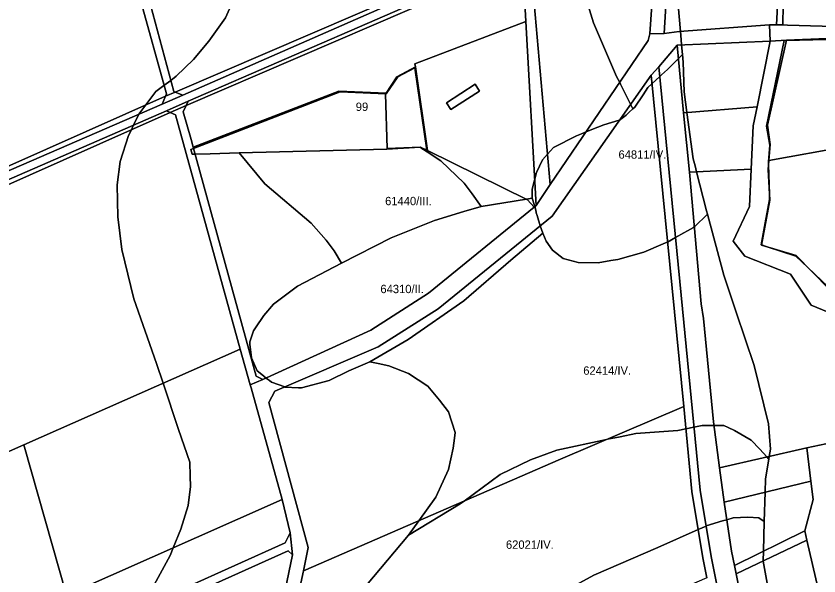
# Model space of a CAD drawing. Extents: x -522079 to -518833, y -1142400 to -1139961.
# Drawn here: x -520985.3 to -520504.9, y -1141508 to -1141173.1 of the extents above; entities that cross this region are included whole.
import ezdxf

# ---------------------------------------------------------------- set-up
doc = ezdxf.new("R2010")
doc.units = 0
for name, color, linetype in [('95560013', 7, 'Continuous'), ('95600013', 7, 'Continuous'), ('95610013', 7, 'Continuous'), ('95620013', 7, 'Continuous'), ('95630013', 7, 'Continuous'), ('95640013', 7, 'Continuous'), ('95660013', 7, 'Continuous')]:
    doc.layers.add(name, color=color, linetype=linetype)

msp = doc.modelspace()

# ---------------------------------------------------------------- linework, layer by layer
at = {"layer": '95560013'}
for points in [[(-520948.18, -1141008.97), (-520939.75, -1141038.42), (-520928.14, -1141079.25), (-520914.59, -1141129.89), (-520890.98, -1141218.17), (-520890.16, -1141218.54), (-520895.96, -1141221.04), (-520895.4, -1141219.71), (-520927.66, -1141102.94), (-520964.29, -1140970.32), (-520970.5, -1140967.09), (-520956.56, -1140961.79), (-520959.78, -1140968.46), (-520955.5, -1140983.4), (-520952.2, -1140994.93)], [(-520895.4, -1141219.71), (-520895.96, -1141221.04), (-521038.45, -1141284.46), (-521072.62, -1141164.33), (-521112.83, -1141022.98), (-521082.18, -1141009.47), (-521026.59, -1140987.63), (-520970.5, -1140967.09), (-520964.29, -1140970.32), (-520927.66, -1141102.94)], [(-520914.59, -1141129.89), (-520847.24, -1141100.33), (-520846.14, -1141104.23), (-520733.88, -1141082.24), (-520727.16, -1141148.38), (-520890.16, -1141218.54), (-520890.98, -1141218.17)], [(-520851.22, -1141372.34), (-520980.65, -1141429.68), (-521109.72, -1141486.85), (-521149.23, -1141347.36), (-521147.68, -1141344.03), (-520893.13, -1141230.74), (-520889.86, -1141232.13)], [(-520980.65, -1141429.68), (-520851.22, -1141372.34), (-520845.27, -1141393.64), (-520844.73, -1141395.54), (-520826.14, -1141462.3), (-520955.18, -1141519.6)], [(-520659.49, -1141438.15), (-520585.72, -1141406.64), (-520580.93, -1141457.51), (-520574.39, -1141497.17), (-520572, -1141509.22), (-520635.55, -1141536.73), (-520726.9, -1141576.27), (-520838.97, -1141624.77), (-520813.35, -1141504.9)], [(-520980.65, -1141429.68), (-520955.18, -1141519.6), (-521084.21, -1141576.91), (-521109.72, -1141486.85)], [(-520821.3, -1141482.16), (-520824.28, -1141488.21), (-520974.97, -1141555.99), (-521072.78, -1141598.79), (-521078.78, -1141596.05), (-521084.21, -1141576.91), (-520955.18, -1141519.6), (-520826.14, -1141462.3)], [(-520819.82, -1141495.44), (-520822.47, -1141493.04), (-520972.97, -1141560.63), (-521070.28, -1141603.2), (-521076.03, -1141605.72), (-521077.42, -1141600.82), (-521072.78, -1141598.79), (-520974.97, -1141555.99), (-520824.28, -1141488.21), (-520821.3, -1141482.16)], [(-520822.47, -1141493.04), (-520819.82, -1141495.44), (-520847.36, -1141628.04), (-520954.68, -1141675.43), (-521044.98, -1141715.3), (-521058.67, -1141667), (-521074.66, -1141610.52), (-521070.28, -1141603.2), (-520972.97, -1141560.63)]]:
    msp.add_lwpolyline(points, close=True, dxfattribs=at)
at = {"layer": '95600013'}
msp.add_lwpolyline([(-520879.25, -1141251.61), (-520880.53, -1141246.97), (-520885.33, -1141230.38), (-520883.56, -1141226.59), (-520683.09, -1141140.3), (-520681.18, -1141161.32), (-520680.34, -1141176.38), (-520746.65, -1141201.66), (-520746.38, -1141203.48), (-520757.5, -1141209.45), (-520763.86, -1141219.18), (-520792.12, -1141217.97)], close=True, dxfattribs=at)
at = {"layer": '95610013'}
for points in [[(-520597.46, -1141183.55), (-520594.25, -1141129.86), (-520552.98, -1141119.42), (-520553, -1141122.43), (-520562.26, -1141141.67), (-520551.87, -1141154.33), (-520536.94, -1141152.14), (-520531.44, -1141160.96), (-520529.73, -1141167.05), (-520530.26, -1141178.39), (-520534.49, -1141178.34), (-520588.63, -1141182.42)], [(-520432.59, -1141179.7), (-520440.68, -1141181.04), (-520523.78, -1141178.47), (-520526.48, -1141178.44), (-520526.38, -1141166.45), (-520421.91, -1141158.52), (-520408.18, -1141157.48), (-520425.27, -1141175.41)], [(-520679.28, -1141282.96), (-520739.03, -1141253.62), (-520746.38, -1141203.48), (-520746.65, -1141201.66), (-520680.34, -1141176.38), (-520674.18, -1141286.49), (-520675.31, -1141287.41)], [(-520589.77, -1141190.43), (-520534.17, -1141188.18), (-520541.94, -1141227.47), (-520585.84, -1141231.02)], [(-520727.76, -1141224.94), (-520725.18, -1141228.99), (-520707.92, -1141217.98), (-520710.51, -1141213.9)], [(-520585.84, -1141231.02), (-520541.94, -1141227.47), (-520544.19, -1141238.83), (-520545.37, -1141264.63), (-520582.4, -1141266.58)], [(-520534.35, -1141283.17), (-520535.3, -1141264.93), (-520534.84, -1141259.42), (-520488.31, -1141251.1), (-520469.72, -1141352.88), (-520465.21, -1141361), (-520463.1, -1141373.93), (-520471.76, -1141351.9), (-520499.06, -1141336.21), (-520518.61, -1141316.36), (-520539.2, -1141310.09)], [(-520474.23, -1141423.42), (-520512.06, -1141431.3), (-520564.35, -1141443.41), (-520567.96, -1141415.92), (-520573.91, -1141353.97), (-520575.29, -1141345.21), (-520582.4, -1141266.58), (-520545.37, -1141264.63), (-520546.39, -1141287.04), (-520556.25, -1141307.68), (-520549.32, -1141316.76), (-520521.95, -1141327.46), (-520517.94, -1141333.55), (-520509.58, -1141346.13), (-520479.06, -1141358.55)], [(-520509.69, -1141451.35), (-520561.66, -1141463.92), (-520564.35, -1141443.41), (-520512.06, -1141431.3)], [(-520508.38, -1141462.38), (-520513.39, -1141481.08), (-520555.49, -1141501.75), (-520557.24, -1141493.24), (-520561.66, -1141463.92), (-520509.69, -1141451.35)], [(-520513.39, -1141481.08), (-520512.09, -1141486.67), (-520554.45, -1141506.79), (-520555.49, -1141501.75)], [(-520549.23, -1141532.17), (-520554.45, -1141506.79), (-520512.09, -1141486.67), (-520501.99, -1141530.25), (-520478.09, -1141540.57), (-520469.99, -1141514.94), (-520451.9, -1141513.8), (-520438.57, -1141562.32), (-520457.06, -1141558.71), (-520539.75, -1141570.9)]]:
    msp.add_lwpolyline(points, close=True, dxfattribs=at)
msp.add_lwpolyline([(-520561.68, -1141535.49), (-520569.46, -1141496.36), (-520576, -1141456.7), (-520587.35, -1141340.09), (-520600.66, -1141203.4), (-520589.77, -1141190.43), (-520585.84, -1141231.02), (-520582.4, -1141266.58), (-520575.29, -1141345.21), (-520573.91, -1141353.97), (-520567.96, -1141415.92), (-520564.35, -1141443.41), (-520561.66, -1141463.92), (-520557.24, -1141493.24), (-520555.49, -1141501.75), (-520554.45, -1141506.79), (-520549.23, -1141532.17)], dxfattribs=at)
at = {"layer": '95620013'}
for points in [[(-520607.02, -1141187.64), (-520665.65, -1141273.94), (-520677.78, -1141138.02), (-520612.8, -1141110.04), (-520601.54, -1141117.64), (-520606.07, -1141183.78)], [(-520813.35, -1141504.9), (-520810.51, -1141490.93), (-520834.09, -1141404.31), (-520830.45, -1141397.51), (-520768.7, -1141371.01), (-520732.72, -1141348.25), (-520664.52, -1141292.81), (-520605.35, -1141208.42), (-520585.72, -1141406.64), (-520659.49, -1141438.15)], [(-520837.57, -1141390.54), (-520841.7, -1141388.53), (-520879.25, -1141251.61), (-520792.12, -1141217.97), (-520763.86, -1141219.18), (-520764.2, -1141219.7), (-520763.26, -1141252.34), (-520743.39, -1141251.48), (-520739.03, -1141253.62), (-520679.28, -1141282.96), (-520675.31, -1141287.41), (-520738.6, -1141338.95), (-520773.04, -1141360.9)]]:
    msp.add_lwpolyline(points, close=True, dxfattribs=at)
at = {"layer": '95630013'}
for points in [[(-520526.38, -1141166.45), (-520526.48, -1141178.44), (-520530.26, -1141178.39), (-520529.73, -1141167.05)], [(-520479.06, -1141358.55), (-520509.58, -1141346.13), (-520517.94, -1141333.55), (-520521.95, -1141327.46), (-520549.32, -1141316.76), (-520556.25, -1141307.68), (-520546.39, -1141287.04), (-520545.37, -1141264.63), (-520544.19, -1141238.83), (-520541.94, -1141227.47), (-520534.17, -1141188.18), (-520524.27, -1141187.6), (-520535.7, -1141238.47), (-520534.05, -1141249.88), (-520534.84, -1141259.42), (-520535.3, -1141264.93), (-520534.35, -1141283.17), (-520539.2, -1141310.09), (-520518.61, -1141316.36), (-520499.06, -1141336.21)], [(-520501.99, -1141530.25), (-520512.09, -1141486.67), (-520513.39, -1141481.08), (-520508.38, -1141462.38), (-520509.69, -1141451.35), (-520512.06, -1141431.3), (-520474.23, -1141423.42)]]:
    msp.add_lwpolyline(points, dxfattribs=at)
at = {"layer": '95640013'}
for points in [[(-521027.41, -1141281.92), (-520897.83, -1141225.78), (-520885.55, -1141220.5), (-520708.05, -1141142.54), (-520688.68, -1141134.03), (-520675.02, -1141128.07), (-520610.52, -1141099.9), (-520605.48, -1141096), (-520603.47, -1141094.45), (-520599.33, -1141085.41), (-520601.54, -1141117.64), (-520612.8, -1141110.04), (-520615.64, -1141108.13), (-520683.34, -1141137.56), (-520705.75, -1141147.3), (-520882.39, -1141224.1), (-520895.38, -1141229.74), (-521025.25, -1141286.2)], [(-520594.25, -1141129.86), (-520597.46, -1141183.55), (-520606.07, -1141183.78), (-520601.54, -1141117.64)], [(-520847.36, -1141628.04), (-520819.82, -1141495.44), (-520821.3, -1141482.16), (-520826.14, -1141462.3), (-520844.73, -1141395.54), (-520845.27, -1141393.64), (-520837.57, -1141390.54), (-520773.04, -1141360.9), (-520738.6, -1141338.95), (-520675.31, -1141287.41), (-520674.18, -1141286.49), (-520665.65, -1141273.94), (-520607.02, -1141187.64), (-520606.07, -1141183.78), (-520597.46, -1141183.55), (-520588.63, -1141182.42), (-520534.49, -1141178.34), (-520534.17, -1141188.18), (-520589.77, -1141190.43), (-520600.66, -1141203.4), (-520605.35, -1141208.42), (-520664.52, -1141292.81), (-520732.72, -1141348.25), (-520768.7, -1141371.01), (-520830.45, -1141397.51), (-520834.09, -1141404.31), (-520810.51, -1141490.93), (-520813.35, -1141504.9), (-520838.97, -1141624.77)], [(-520500.08, -1141186.63), (-520524.27, -1141187.6), (-520534.17, -1141188.18), (-520534.49, -1141178.34), (-520530.26, -1141178.39), (-520526.48, -1141178.44), (-520523.78, -1141178.47), (-520440.68, -1141181.04)], [(-520572, -1141509.22), (-520574.39, -1141497.17), (-520580.93, -1141457.51), (-520585.72, -1141406.64), (-520605.35, -1141208.42), (-520600.66, -1141203.4), (-520587.35, -1141340.09), (-520576, -1141456.7), (-520569.46, -1141496.36), (-520561.68, -1141535.49)]]:
    msp.add_lwpolyline(points, dxfattribs=at)
for points in [[(-520890.16, -1141218.54), (-520727.16, -1141148.38), (-520686.99, -1141131.09), (-520688.68, -1141134.03), (-520708.05, -1141142.54), (-520885.55, -1141220.5)], [(-520683.34, -1141137.56), (-520683.09, -1141140.3), (-520883.56, -1141226.59), (-520882.39, -1141224.1), (-520705.75, -1141147.3)], [(-520683.09, -1141140.3), (-520677.78, -1141138.02), (-520665.65, -1141273.94), (-520674.18, -1141286.49), (-520680.34, -1141176.38), (-520681.18, -1141161.32)], [(-520535.7, -1141238.47), (-520524.27, -1141187.6), (-520500.08, -1141186.63), (-520488.31, -1141251.1), (-520534.84, -1141259.42), (-520534.05, -1141249.88)], [(-520743.39, -1141251.48), (-520763.26, -1141252.34), (-520764.2, -1141219.7), (-520763.86, -1141219.18), (-520757.5, -1141209.45), (-520746.38, -1141203.48), (-520739.03, -1141253.62)], [(-520895.96, -1141221.04), (-520890.16, -1141218.54), (-520885.55, -1141220.5), (-520897.83, -1141225.78)], [(-520727.76, -1141224.94), (-520710.51, -1141213.9), (-520707.92, -1141217.98), (-520725.18, -1141228.99)], [(-520895.96, -1141221.04), (-520897.83, -1141225.78), (-521027.41, -1141281.92), (-521037.84, -1141286.59), (-521038.45, -1141284.46)], [(-520882.39, -1141224.1), (-520883.56, -1141226.59), (-520893.13, -1141230.74), (-520895.38, -1141229.74)], [(-520837.57, -1141390.54), (-520845.27, -1141393.64), (-520851.22, -1141372.34), (-520889.86, -1141232.13), (-520893.13, -1141230.74), (-520883.56, -1141226.59), (-520885.33, -1141230.38), (-520880.53, -1141246.97), (-520879.25, -1141251.61), (-520841.7, -1141388.53)], [(-520893.13, -1141230.74), (-521147.68, -1141344.03), (-521146.08, -1141340.6), (-521025.25, -1141286.2), (-520895.38, -1141229.74)]]:
    msp.add_lwpolyline(points, close=True, dxfattribs=at)
at = {"layer": '95660013'}
for points in [[(-520854.61, -1141161.87), (-520860.04, -1141174.14), (-520870.01, -1141188.23), (-520879.07, -1141199.13), (-520889.49, -1141209.13), (-520892.75, -1141211.56), (-520896.82, -1141214.58), (-520901.72, -1141218.22), (-520907.65, -1141226.24), (-520911.78, -1141231.82), (-520912.14, -1141232.31), (-520915, -1141238.27), (-520916.34, -1141241.07), (-520918.03, -1141244.58), (-520923.01, -1141260.03), (-520924.82, -1141274.12), (-520924.37, -1141293.2), (-520922.11, -1141312.75), (-520914.86, -1141342.28), (-520901.27, -1141380.91), (-520897.33, -1141392.76), (-520888.13, -1141420.45), (-520881.34, -1141439.99), (-520881.08, -1141448.32), (-520880.88, -1141454.53), (-520882.24, -1141465.89), (-520886.77, -1141479.98), (-520891.25, -1141491.21), (-520893.11, -1141495.88), (-520906.25, -1141519.97)], [(-520906.25, -1141519.97), (-520893.11, -1141495.88), (-520891.25, -1141491.21), (-520886.77, -1141479.98), (-520882.24, -1141465.89), (-520880.88, -1141454.53), (-520881.08, -1141448.32), (-520881.34, -1141439.99), (-520888.13, -1141420.45), (-520897.33, -1141392.76), (-520901.27, -1141380.91), (-520914.86, -1141342.28), (-520922.11, -1141312.75), (-520924.37, -1141293.2), (-520924.82, -1141274.12), (-520923.01, -1141260.03), (-520918.03, -1141244.58), (-520916.34, -1141241.07), (-520915, -1141238.27), (-520912.14, -1141232.31), (-520911.78, -1141231.82), (-520907.65, -1141226.24), (-520901.72, -1141218.22), (-520896.82, -1141214.58), (-520892.75, -1141211.56), (-520889.49, -1141209.13), (-520879.07, -1141199.13), (-520870.01, -1141188.23), (-520860.04, -1141174.14), (-520854.61, -1141161.87)], [(-520644.35, -1141162.05), (-520639.78, -1141177.21), (-520625.97, -1141209.18), (-520624.13, -1141212.83), (-520623.62, -1141213.83), (-520617.56, -1141225.84), (-520616.21, -1141228.52), (-520618.44, -1141230.62), (-520620.26, -1141232.34), (-520624.21, -1141235.31), (-520624.35, -1141235.42), (-520633.7, -1141238.2), (-520640.88, -1141241.06), (-520644.21, -1141242.38), (-520646.99, -1141243.49), (-520649.92, -1141244.66), (-520663.65, -1141251.69), (-520667.27, -1141255.8), (-520670.23, -1141259.17), (-520673.89, -1141266.75), (-520675.03, -1141271.22), (-520676.44, -1141276.73), (-520676.44, -1141282.14), (-520679.84, -1141282.68), (-520707.07, -1141287), (-520712.45, -1141279.5), (-520717.11, -1141273), (-520731.06, -1141259.66), (-520739.34, -1141254.29), (-520739.47, -1141253.4), (-520746.78, -1141204), (-520756.85, -1141209.44), (-520763.8, -1141219.61), (-520764.13, -1141219.59), (-520791.31, -1141218.35), (-520871.38, -1141249.26), (-520879.08, -1141252.24), (-520880.78, -1141252.89), (-520880, -1141255.73), (-520878.14, -1141255.68), (-520869.12, -1141255.45), (-520851.89, -1141255.02), (-520836.39, -1141273.44), (-520808.7, -1141297.06), (-520799.76, -1141307.12), (-520794.96, -1141313.47), (-520790.6, -1141320.91), (-520816.82, -1141334.59), (-520831.31, -1141345.42), (-520837, -1141352.26), (-520842.08, -1141359.69), (-520843.25, -1141361.39), (-520845.52, -1141367.94), (-520845.35, -1141369.42), (-520844.38, -1141377.63), (-520840.97, -1141385.33), (-520838.35, -1141387.44), (-520835.61, -1141389.64), (-520834.78, -1141390.3), (-520833.74, -1141391.13), (-520832.45, -1141392.17), (-520824.58, -1141394.99), (-520824.49, -1141395.02), (-520816.33, -1141395.49), (-520814.55, -1141395.59), (-520798.06, -1141391.03), (-520786.13, -1141385.33), (-520773.63, -1141379.92), (-520768.66, -1141380.95), (-520762.28, -1141382.28), (-520750.59, -1141386.97), (-520738.9, -1141394.59), (-520731.89, -1141402.8), (-520726.63, -1141409.84), (-520722.54, -1141422.15), (-520722.98, -1141425.69), (-520723.7, -1141431.53), (-520726.63, -1141444.43), (-520734.22, -1141460.84), (-520744.32, -1141474.95), (-520750.59, -1141483.71), (-520775.72, -1141513.61)], [(-520589.2, -1141166.56), (-520587.79, -1141182.35), (-520587.59, -1141184.62), (-520587.08, -1141190.32), (-520586.56, -1141196.12), (-520587.8, -1141197.35), (-520588.98, -1141198.53), (-520595.57, -1141205.08), (-520599.04, -1141208.31), (-520599.49, -1141208.72), (-520600.09, -1141209.27), (-520604.83, -1141213.68), (-520607.26, -1141215.93), (-520610.17, -1141220.2), (-520615.14, -1141227.51), (-520616.21, -1141228.52), (-520617.56, -1141225.84), (-520623.62, -1141213.83), (-520624.13, -1141212.83), (-520625.97, -1141209.18), (-520639.78, -1141177.21), (-520644.35, -1141162.05)], [(-520533.32, -1141526.62), (-520538.18, -1141499.21), (-520538.17, -1141499.06), (-520538.02, -1141493.17), (-520537.57, -1141475.45), (-520537.16, -1141457.99), (-520536.96, -1141449.86), (-520534.94, -1141438.08), (-520534.67, -1141436.53), (-520533.93, -1141432.19), (-520535.14, -1141416.96), (-520543.64, -1141382.23), (-520554.4, -1141350.22), (-520559.25, -1141335.8), (-520560.23, -1141332.87), (-520561.86, -1141328.01), (-520571.65, -1141291.62), (-520572.19, -1141289.63), (-520578.1, -1141266.35), (-520579.04, -1141262.66), (-520580.09, -1141258.56), (-520583.85, -1141230.86), (-520585.55, -1141218.35), (-520586.16, -1141200.68), (-520586.56, -1141196.12), (-520587.08, -1141190.32), (-520587.59, -1141184.62), (-520587.79, -1141182.35), (-520589.2, -1141166.56)], [(-520499.45, -1141335.14), (-520511.59, -1141323.48), (-520518.63, -1141316.73), (-520536.52, -1141310.91), (-520539.19, -1141310.03), (-520539.53, -1141309.92), (-520537.07, -1141296.8), (-520534.44, -1141282.78), (-520534.53, -1141279.78), (-520534.53, -1141279.71), (-520535.07, -1141262.19), (-520535.13, -1141260.34), (-520534.37, -1141250.38), (-520536.29, -1141238.97), (-520525.78, -1141187.83), (-520524.31, -1141187.79), (-520500.85, -1141187.11)], [(-520500.85, -1141187.11), (-520524.31, -1141187.79), (-520525.78, -1141187.83), (-520536.29, -1141238.97), (-520534.37, -1141250.38), (-520535.13, -1141260.34), (-520535.07, -1141262.19), (-520534.53, -1141279.71), (-520534.53, -1141279.78), (-520534.44, -1141282.78), (-520537.07, -1141296.8), (-520539.53, -1141309.92), (-520539.19, -1141310.03), (-520536.52, -1141310.91), (-520518.63, -1141316.73), (-520511.59, -1141323.48), (-520499.45, -1141335.14)], [(-520775.72, -1141513.61), (-520750.59, -1141483.71), (-520719.61, -1141464.95), (-520717.23, -1141463.2), (-520695.65, -1141447.36), (-520677.53, -1141438.57), (-520661.75, -1141432.7), (-520631.92, -1141426.37), (-520631.36, -1141426.25), (-520623.91, -1141424.71), (-520614.41, -1141422.74), (-520589.28, -1141420.98), (-520584.46, -1141420.01), (-520579.66, -1141419.04), (-520574.67, -1141418.04), (-520571.52, -1141418.04), (-520567.68, -1141418.04), (-520561.82, -1141418.04), (-520559.11, -1141419.28), (-520555.39, -1141420.98), (-520545.45, -1141426.84), (-520540.19, -1141432.11), (-520536.02, -1141436.85), (-520534.94, -1141438.08), (-520536.96, -1141449.86), (-520537.16, -1141457.99), (-520537.57, -1141475.45), (-520540.8, -1141473.17), (-520547.46, -1141472.82), (-520556.21, -1141473.17), (-520560.09, -1141474.36), (-520562.57, -1141475.11), (-520572.31, -1141478.09), (-520572.46, -1141478.16), (-520574.86, -1141479.23), (-520577.18, -1141480.26), (-520601.37, -1141491.08), (-520639.54, -1141507.59), (-520673.15, -1141525.85)], [(-520673.15, -1141525.85), (-520639.54, -1141507.59), (-520601.37, -1141491.08), (-520577.18, -1141480.26), (-520574.86, -1141479.23), (-520572.46, -1141478.16), (-520572.31, -1141478.09), (-520562.57, -1141475.11), (-520560.09, -1141474.36), (-520556.21, -1141473.17), (-520547.46, -1141472.82), (-520540.8, -1141473.17), (-520537.57, -1141475.45), (-520538.02, -1141493.17), (-520538.17, -1141499.06), (-520538.18, -1141499.21), (-520533.32, -1141526.62)]]:
    msp.add_lwpolyline(points, dxfattribs=at)
for points in [[(-520629.39, -1141319.4), (-520636.91, -1141320.73), (-520648.9, -1141320.43), (-520657.95, -1141318.09), (-520664.38, -1141313.1), (-520668.18, -1141307.83), (-520670.19, -1141302.95), (-520671.61, -1141298.57), (-520673.6, -1141292.41), (-520674, -1141290.74), (-520674.02, -1141290.67), (-520674.36, -1141289.21), (-520674.87, -1141287.05), (-520675.02, -1141286.42), (-520676.44, -1141282.14), (-520676.44, -1141276.73), (-520675.03, -1141271.22), (-520673.89, -1141266.75), (-520670.23, -1141259.17), (-520667.27, -1141255.8), (-520663.65, -1141251.69), (-520649.92, -1141244.66), (-520646.99, -1141243.49), (-520644.21, -1141242.38), (-520640.88, -1141241.06), (-520633.7, -1141238.2), (-520624.35, -1141235.42), (-520624.21, -1141235.31), (-520620.26, -1141232.34), (-520618.44, -1141230.62), (-520616.21, -1141228.52), (-520615.14, -1141227.51), (-520610.17, -1141220.2), (-520607.26, -1141215.93), (-520604.83, -1141213.68), (-520600.09, -1141209.27), (-520599.49, -1141208.72), (-520599.04, -1141208.31), (-520595.57, -1141205.08), (-520588.98, -1141198.53), (-520587.8, -1141197.35), (-520586.56, -1141196.12), (-520586.16, -1141200.68), (-520585.55, -1141218.35), (-520583.85, -1141230.86), (-520580.09, -1141258.56), (-520579.04, -1141262.66), (-520578.1, -1141266.35), (-520572.19, -1141289.63), (-520571.65, -1141291.62), (-520579.45, -1141299.16), (-520579.93, -1141299.62), (-520583.5, -1141301.61), (-520585.65, -1141302.81), (-520590.71, -1141305.62), (-520595.46, -1141308.27), (-520595.71, -1141308.41), (-520598.01, -1141309.37), (-520609.74, -1141314.27), (-520625.23, -1141318.67)], [(-520746.78, -1141204), (-520739.47, -1141253.4), (-520739.34, -1141254.29), (-520743.07, -1141251.94), (-520743.59, -1141251.61), (-520763.46, -1141252.81), (-520851.89, -1141255.02), (-520869.12, -1141255.45), (-520878.14, -1141255.68), (-520880, -1141255.73), (-520880.78, -1141252.89), (-520879.08, -1141252.24), (-520871.38, -1141249.26), (-520791.31, -1141218.35), (-520764.13, -1141219.59), (-520763.8, -1141219.61), (-520756.85, -1141209.44)], [(-520739.34, -1141254.29), (-520731.06, -1141259.66), (-520717.11, -1141273), (-520712.45, -1141279.5), (-520707.07, -1141287), (-520717.31, -1141290.05), (-520734.99, -1141295.31), (-520760.94, -1141305.81), (-520790.6, -1141320.91), (-520794.96, -1141313.47), (-520799.76, -1141307.12), (-520808.7, -1141297.06), (-520836.39, -1141273.44), (-520851.89, -1141255.02), (-520763.46, -1141252.81), (-520743.59, -1141251.61), (-520743.07, -1141251.94)], [(-520670.19, -1141302.95), (-520689.23, -1141319.2), (-520717.36, -1141343.43), (-520750.61, -1141366.52), (-520773.63, -1141379.92), (-520786.13, -1141385.33), (-520798.06, -1141391.03), (-520814.55, -1141395.59), (-520816.33, -1141395.49), (-520824.49, -1141395.02), (-520824.58, -1141394.99), (-520832.45, -1141392.17), (-520833.74, -1141391.13), (-520834.78, -1141390.3), (-520835.61, -1141389.64), (-520838.35, -1141387.44), (-520840.97, -1141385.33), (-520844.38, -1141377.63), (-520845.35, -1141369.42), (-520845.52, -1141367.94), (-520843.25, -1141361.39), (-520842.08, -1141359.69), (-520837, -1141352.26), (-520831.31, -1141345.42), (-520816.82, -1141334.59), (-520790.6, -1141320.91), (-520760.94, -1141305.81), (-520734.99, -1141295.31), (-520717.31, -1141290.05), (-520707.07, -1141287), (-520679.84, -1141282.68), (-520676.44, -1141282.14), (-520675.02, -1141286.42), (-520674.87, -1141287.05), (-520674.36, -1141289.21), (-520674.02, -1141290.67), (-520674, -1141290.74), (-520673.6, -1141292.41), (-520671.61, -1141298.57)], [(-520534.94, -1141438.08), (-520536.02, -1141436.85), (-520540.19, -1141432.11), (-520545.45, -1141426.84), (-520555.39, -1141420.98), (-520559.11, -1141419.28), (-520561.82, -1141418.04), (-520567.68, -1141418.04), (-520571.52, -1141418.04), (-520574.67, -1141418.04), (-520579.66, -1141419.04), (-520584.46, -1141420.01), (-520589.28, -1141420.98), (-520614.41, -1141422.74), (-520623.91, -1141424.71), (-520631.36, -1141426.25), (-520631.92, -1141426.37), (-520661.75, -1141432.7), (-520677.53, -1141438.57), (-520695.65, -1141447.36), (-520717.23, -1141463.2), (-520719.61, -1141464.95), (-520750.59, -1141483.71), (-520744.32, -1141474.95), (-520734.22, -1141460.84), (-520726.63, -1141444.43), (-520723.7, -1141431.53), (-520722.98, -1141425.69), (-520722.54, -1141422.15), (-520726.63, -1141409.84), (-520731.89, -1141402.8), (-520738.9, -1141394.59), (-520750.59, -1141386.97), (-520762.28, -1141382.28), (-520768.66, -1141380.95), (-520773.63, -1141379.92), (-520750.61, -1141366.52), (-520717.36, -1141343.43), (-520689.23, -1141319.2), (-520670.19, -1141302.95), (-520668.18, -1141307.83), (-520664.38, -1141313.1), (-520657.95, -1141318.09), (-520648.9, -1141320.43), (-520636.91, -1141320.73), (-520629.39, -1141319.4), (-520625.23, -1141318.67), (-520609.74, -1141314.27), (-520598.01, -1141309.37), (-520595.71, -1141308.41), (-520595.46, -1141308.27), (-520590.71, -1141305.62), (-520585.65, -1141302.81), (-520583.5, -1141301.61), (-520579.93, -1141299.62), (-520579.45, -1141299.16), (-520571.65, -1141291.62), (-520561.86, -1141328.01), (-520560.23, -1141332.87), (-520559.25, -1141335.8), (-520554.4, -1141350.22), (-520543.64, -1141382.23), (-520535.14, -1141416.96), (-520533.93, -1141432.19), (-520534.67, -1141436.53)]]:
    msp.add_lwpolyline(points, close=True, dxfattribs=at)

# ---------------------------------------------------------------- texts
for s, p in [('99', (-520782.05, -1141229.87)), ('64811/IV.', (-520624.84, -1141258.43)), ('61440/III.', (-520764.48, -1141286.26)), ('64310/II.', (-520767.3, -1141338.86)), ('62414/IV.', (-520645.92, -1141387.67)), ('62021/IV.', (-520692.18, -1141491.78))]:
    msp.add_text(s, height=5, rotation=0, dxfattribs=at).set_placement(p)

doc.saveas('drawing.dxf')
